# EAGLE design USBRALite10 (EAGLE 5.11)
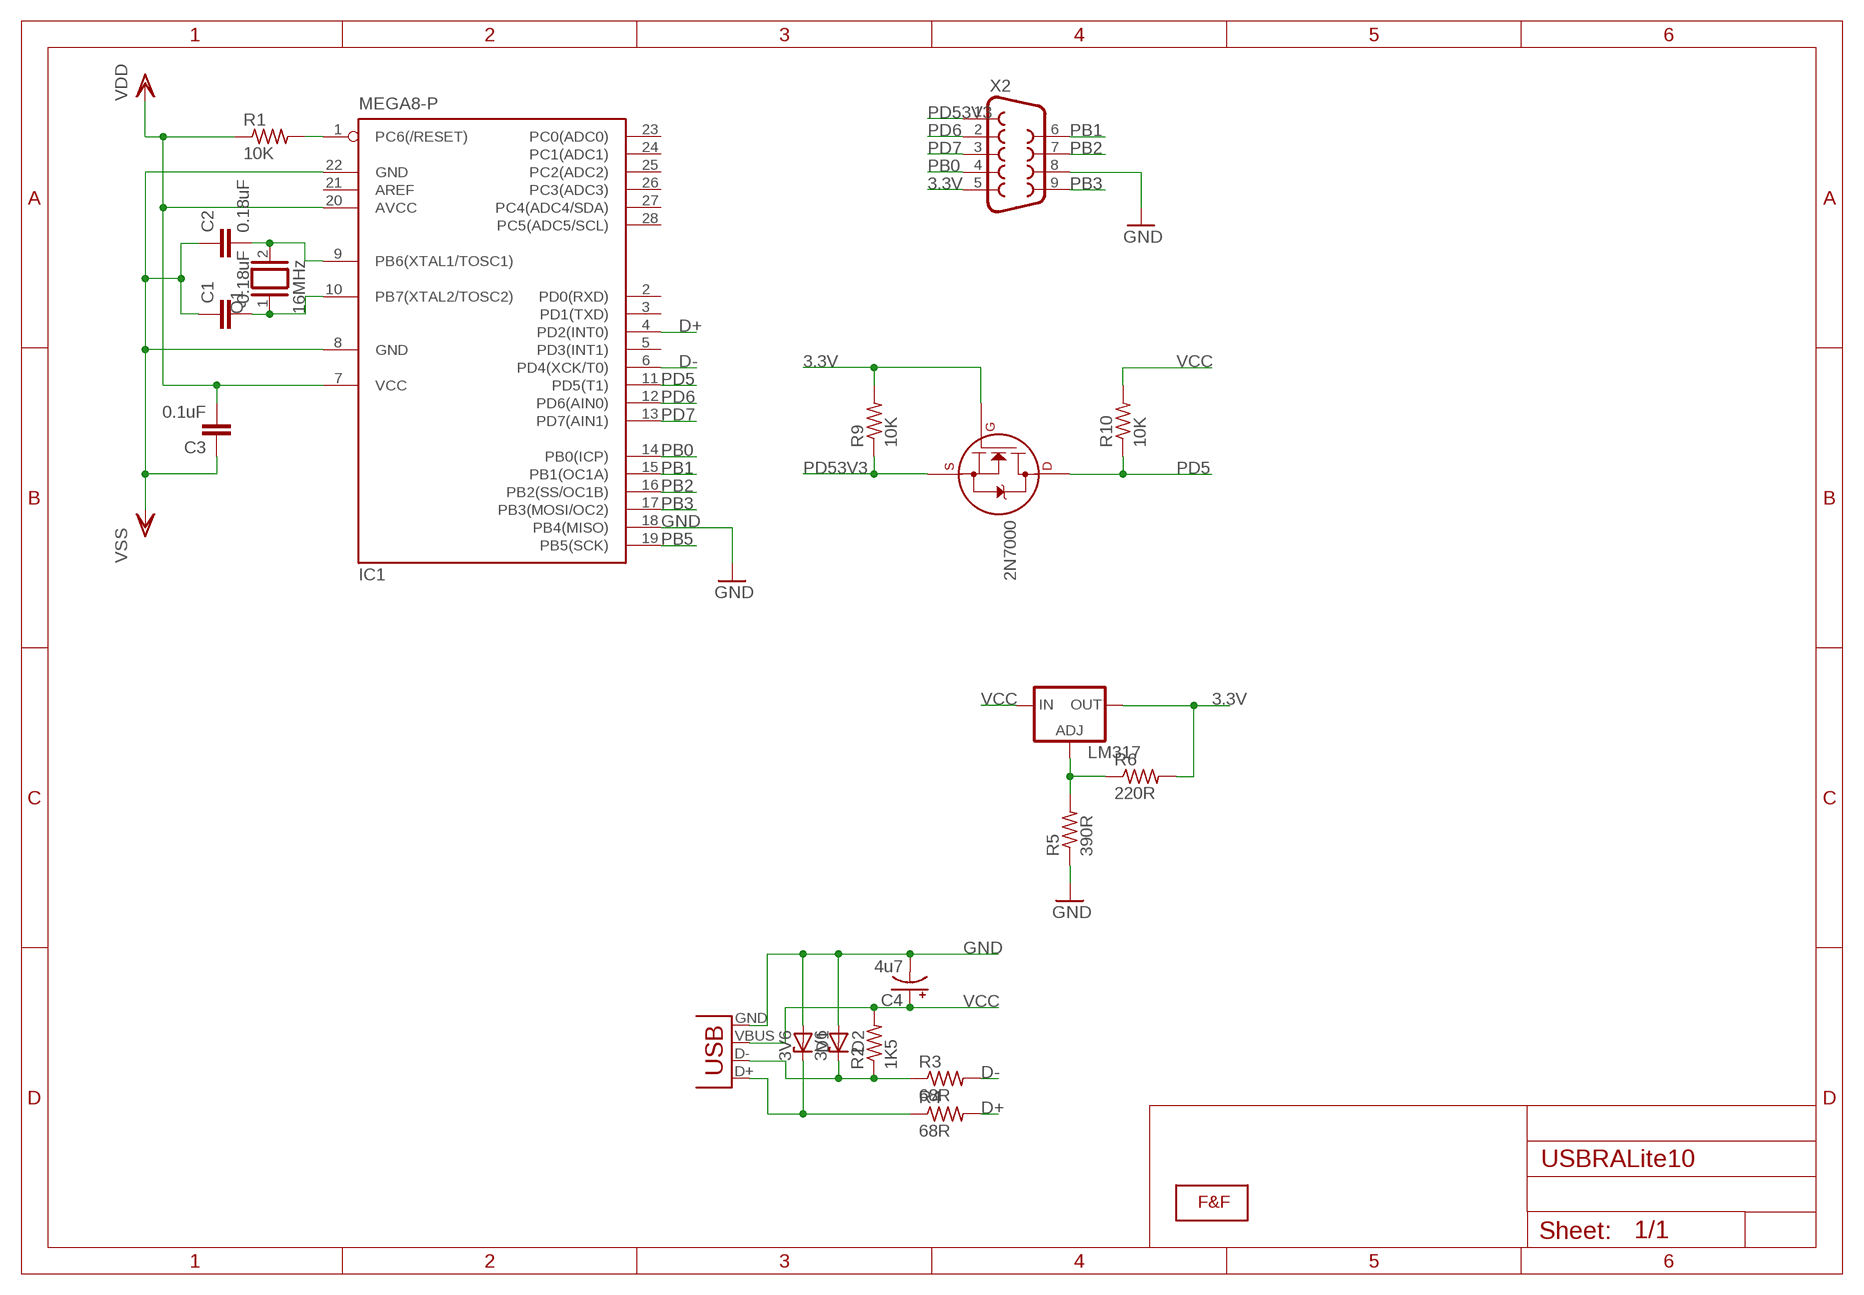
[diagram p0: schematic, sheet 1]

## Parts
2N7000  2N7000_TO92  [TO-92]
C1  0.18uF  CAPPTH  [CAP-PTH-SMALL]
C2  0.18uF  CAPPTH  [CAP-PTH-SMALL]
C3  0.1uF  CAPPTH  [CAP-PTH-SMALL]
C4  4u7  CPOL-USE2.5-6  [E2,5-6]
D1  3V6  ZENER-DIODEZD-5  [ZDIO-5]
D2  3V6  ZENER-DIODEZD-5  [ZDIO-5]
IC1  MEGA8-P  [DIL28-3]
LM317  LM317TS  [317TS]
Q1  16MHz  XTAL/S  [QS]
R1  10K  R-US_0207/10  [0207/10]
R2  1K5  R-US_0207/10  [0207/10]
R3  68R  R-US_0207/10  [0207/10]
R4  68R  R-US_0207/10  [0207/10]
R5  390R  R-US_0207/10  [0207/10]
R6  220R  R-US_0207/10  [0207/10]
R9  10K  R-US_0207/10  [0207/10]
R10  10K  R-US_0207/10  [0207/10]
U$1  LOGOLOGO_WITH_SMOKE_BIG  [LOGO_BIG]
X1  USBPTH  [USB-B-PTH]
X2  DB9MALE  [DB9_MALE]

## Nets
3.3V: 2N7000.2(G) LM317.2(OUT) R6.2 R9.2 X2.5
D+: IC1.4(PD2(INT0)) R4.2
D-: IC1.6(PD4(XCK/T0)) R3.2
GND: C1.1 C2.1 C3.1 C4.- D1.A D2.A IC1.8(GND) IC1.18(PB4(MISO)) IC1.22(GND) R5.1 X1.GND X2.8 ; supply symbol labelled VSS
N$1: IC1.1(PC6(/RESET)) R1.2
N$2: C2.2 IC1.9(PB6(XTAL1/TOSC1)) Q1.2
N$3: C1.2 IC1.10(PB7(XTAL2/TOSC2)) Q1.1
N$5: LM317.1(ADJ) R5.2 R6.1
N$8: D1.C R4.1 X1.D+
N$9: D2.C R2.1 R3.1 X1.D-
PB0: IC1.14(PB0(ICP)) X2.4
PB1: IC1.15(PB1(OC1A)) X2.6
PB2: IC1.16(PB2(SS/OC1B)) X2.7
PB3: IC1.17(PB3(MOSI/OC2)) X2.9
PB5: IC1.19(PB5(SCK))
PD5: 2N7000.3(D) IC1.11(PD5(T1)) R10.1
PD6: IC1.12(PD6(AIN0)) X2.2
PD7: IC1.13(PD7(AIN1)) X2.3
PD53V3: 2N7000.1(S) R9.1 X2.1
VCC: C3.2 C4.+ IC1.7(VCC) IC1.20(AVCC) LM317.3(IN) R1.1 R2.2 R10.2 X1.VBUS ; supply symbol labelled VDD
Unconnected: IC1.2(PD0(RXD)) IC1.3(PD1(TXD)) IC1.5(PD3(INT1)) IC1.21(AREF) IC1.23(PC0(ADC0)) IC1.24(PC1(ADC1)) IC1.25(PC2(ADC2)) IC1.26(PC3(ADC3)) IC1.27(PC4(ADC4/SDA)) IC1.28(PC5(ADC5/SCL))

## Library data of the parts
2N7000 = transistors:2N700*: 2N7000, 2N7002, NDS7002A N-channel enhancement mode MOSFET
C1-C3 = SparkFun:CAP: Capacitor
C4 = adafruit:CPOL-US: POLARIZED CAPACITOR, American symbol
D1 D2 = diode:ZENER-DIODE: Z-Diode
IC1 = atmel:MEGA8-P: MICROCONTROLLER 8 Kbytes FLASH, 1 kbytes SRAM, 512 bytes EEPROM, USART, 4-channel 10 bit ADC, 2-channel 8 bit ADC Pin compatible with Atmega48, ATMega88, ATMega168 Source: avr.lbr; OC_FARNELL: unknown; OC_NEWARK: unknown
LM317 = v-reg:LM317TS: VOLTAGE REGULATOR
Q1 = special:XTAL/S: CRYSTAL
R1-R6 R9 R10 = adafruit:R-US_: RESISTOR, American symbol
U$1 = F&F:LOGO: Faísca e Fumaça Logo
X1 = SparkFun:USB: USB Connectors USB-B-PTH is fully proven SKU : PRT-00139 USB-miniB is fully proven SKU : PRT-00587 USB-A-PCB is untested. USB-A-H is throughly reviewed, but untested. Spark Fun Electronics SKU : PRT-00437 USB-B-SMT is throughly reviewed, but untested. Needs silkscreen touching up. USB-A-S has not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
X2 = SparkFun:DB9: DB9 Connector Standard DB9 (D-Sub 9) serial connector. Can be used for CAN bus as well as RS485 and RS232. Footprint production proven. Spark Fun Electronics SKU : PRT-00429

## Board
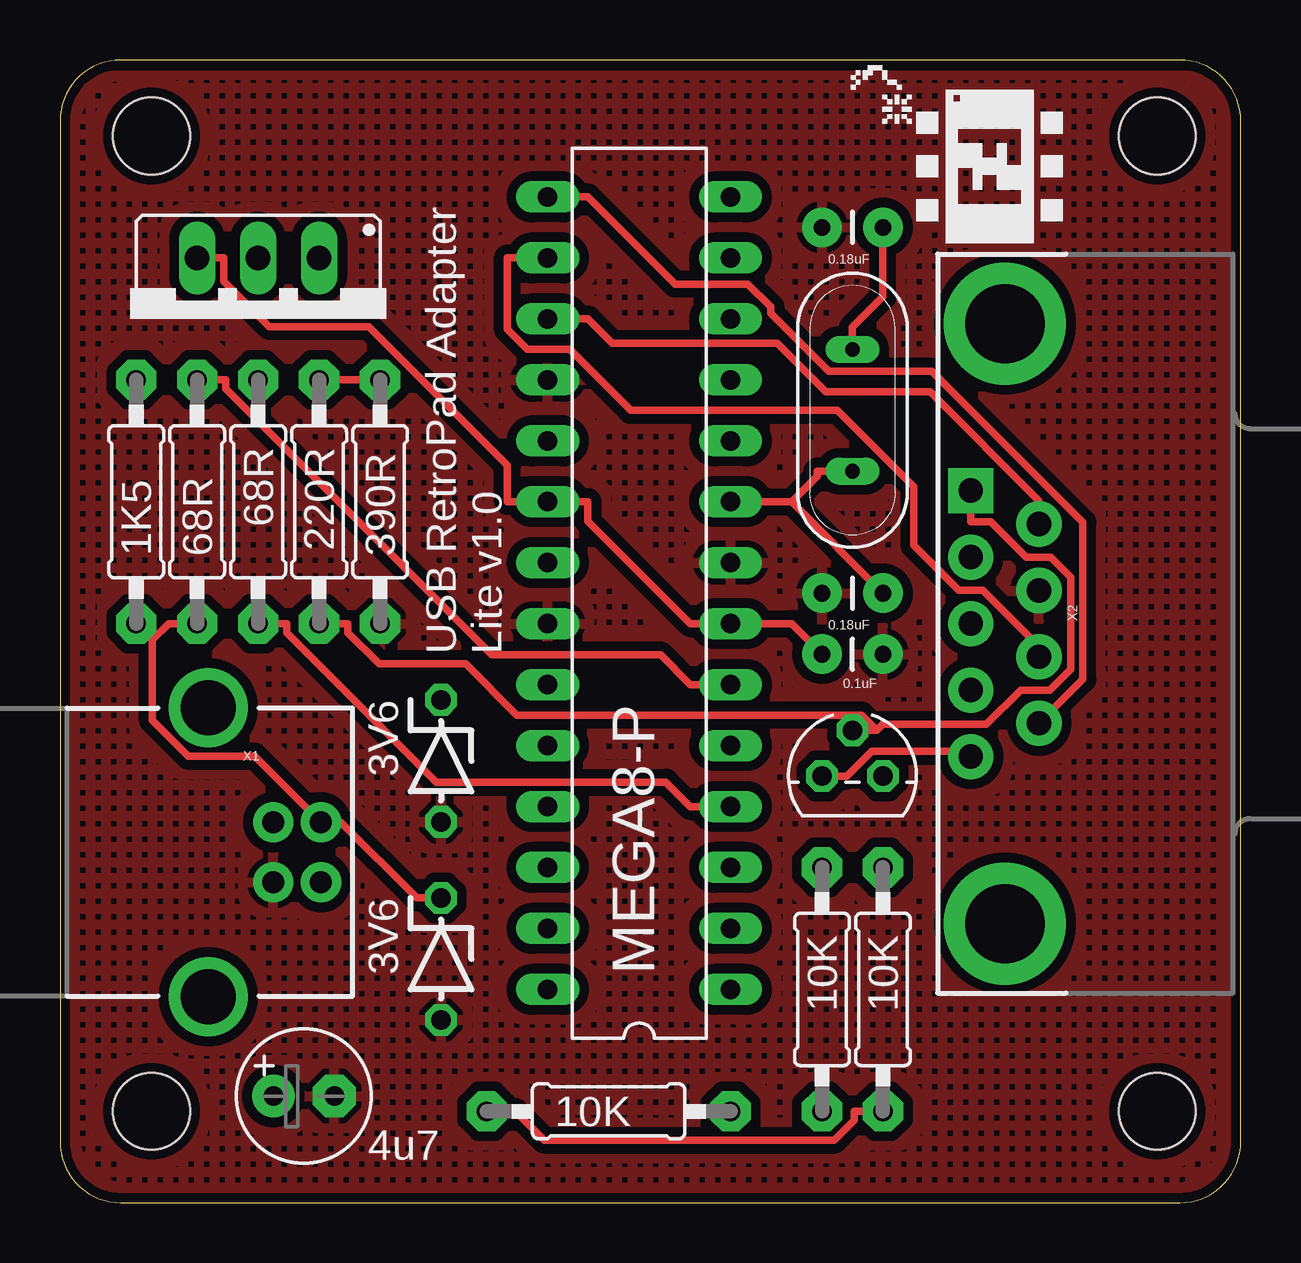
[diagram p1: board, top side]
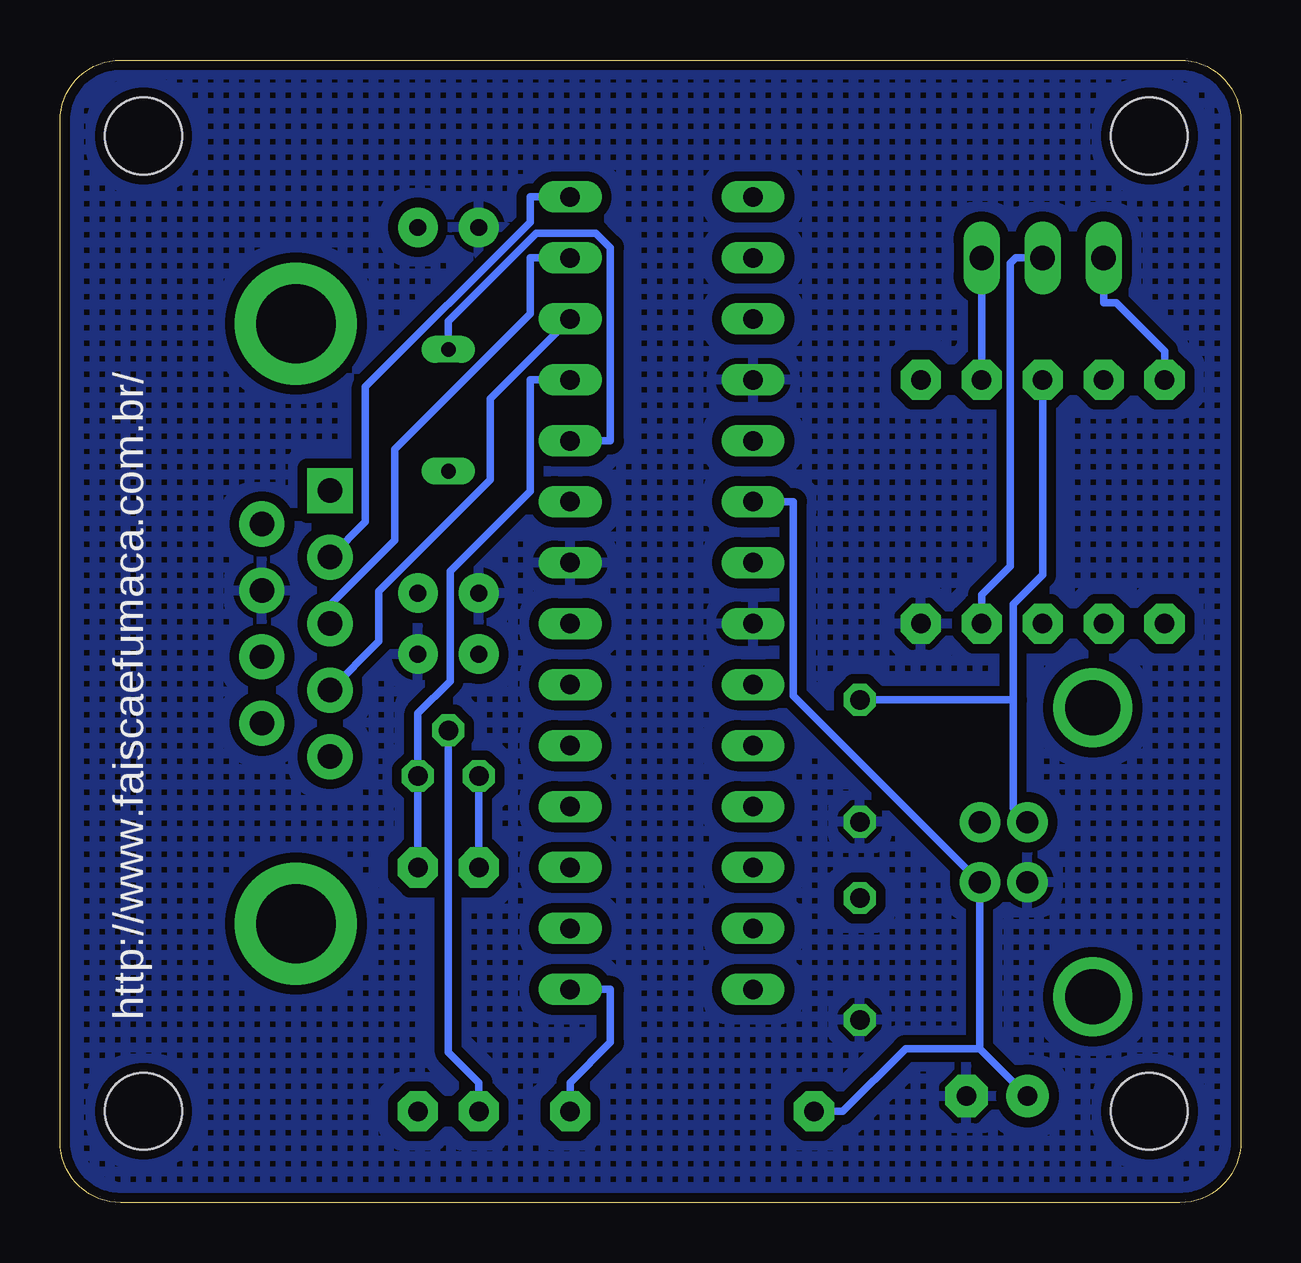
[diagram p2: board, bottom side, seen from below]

Size 49.2 x 47.62 mm. Coordinates in mm from the lower left corner, seen from the top.
Outline: 49.2,45.08 arc90 46.66,47.62 2.54,47.62 arc90 0,45.08 0,2.54 arc90 2.54,0 46.66,0 arc90 49.2,2.54 49.2,45.08
Copper layers (1*16): Top 0.035mm / dielectric 1.5mm / Bottom 0.035mm
Design rules "ITead_rule": minimum track width 6mil, minimum drill 12mil, track to track 6mil, track to pad 6mil, pad to pad 6mil, via to via 6mil, smd to smd 0mil, copper to edge 10mil, drill to drill 10mil, minimum pad ring 10mil, minimum via ring 6mil, stop-mask expansion 2mil, vias tented up to drill 100mil, thermal gap 10mil
Holes 3.2 mm at 3.81,44.45 3.81,3.81 45.72,44.45 45.72,3.81

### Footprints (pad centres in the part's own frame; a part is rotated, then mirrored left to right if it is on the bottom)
TO-92 = drill 0.813 octagon: 1 -1.27,0; 2 0,1.905; 3 1.27,0
CAP-PTH-SMALL = drill 0.7 pad 1.651 round: 1 0,0; 2 2.54,0
E2,5-6 = drill 0.813 pad 1.778 round: + -1.27,0 | drill 0.813 pad 1.778 octagon: - 1.27,0
ZDIO-5 = drill 0.813 octagon: A 2.54,0; C -2.54,0
DIL28-3 = drill 0.813 long: 1 -16.51,-3.81; 2 -13.97,-3.81; 3 -11.43,-3.81; 4 -8.89,-3.81; 5 -6.35,-3.81; 6 -3.81,-3.81; 7 -1.27,-3.81; 8 1.27,-3.81; 9 3.81,-3.81; 10 6.35,-3.81; 11 8.89,-3.81; 12 11.43,-3.81; 13 13.97,-3.81; 14 16.51,-3.81; 15 16.51,3.81; 16 13.97,3.81; 17 11.43,3.81; 18 8.89,3.81; 19 6.35,3.81; 20 3.81,3.81; 21 1.27,3.81; 22 -1.27,3.81; 23 -3.81,3.81; 24 -6.35,3.81; 25 -8.89,3.81; 26 -11.43,3.81; 27 -13.97,3.81; 28 -16.51,3.81
317TS = drill 1.016 long: 1 -2.54,-2.54; 2 0,-2.54; 3 2.54,-2.54
QS = drill 0.61 long: 1 -2.54,0; 2 2.54,0
0207/10 = drill 0.813 pad 1.676 octagon: 1 -5.08,0; 2 5.08,0
USB-B-PTH = drill 0.914 pad 1.676 round: D+ 0,1.25; D- 1.981,1.25; GND 0,-1.25; VBUS 1.981,-1.25 | drill 2.286 round: S1 -2.718,-6.02; S2 -2.718,6.02
DB9_MALE = drill 1.016 pad 1.88 round: 1 5.54,-1.42; 2 2.77,-1.42; 3 0,-1.42; 4 -2.77,-1.42; 6 4.15,1.42; 7 1.38,1.42; 8 -1.38,1.42; 9 -4.15,1.42 | drill 1.016 pad 1.88 square: 5 -5.54,-1.42 | drill 3.302 pad 5.08 round: G1 -12.5,0; G2 12.5,0

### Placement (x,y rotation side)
2N7000  33.02,17.78 0 top
C1  31.75,40.64 0 top
C2  31.75,25.4 0 top
C3  34.29,22.86 180 top
C4  10.16,4.45 0 top
D1  15.88,18.41 270 top
D2  15.88,10.16 270 top
IC1  24.13,25.4 90 top
LM317  8.26,36.83 180 top
Q1  33.02,33.02 270 top
R1  22.86,3.81 0 top
R2  3.17,29.21 90 top
R3  5.71,29.21 90 top
R4  8.26,29.21 270 top
R5  13.34,29.21 90 top
R6  10.79,29.21 270 top
R9  31.75,8.89 270 top
R10  34.29,8.89 270 top
U$1  38.73,43.18 90 top
X1  8.89,14.61 0 top
X2  39.37,24.13 270 top

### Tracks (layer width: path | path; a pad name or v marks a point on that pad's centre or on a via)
3.3V
  Top 0.305: 34.04,19.68 33.4,20.32 19.04,20.32 16.9,22.45 13.29,22.45 11.99,23.76 11.99,24.13 R6.2 | 34.04,19.68 34.28,19.93 38.6,19.93 40.04,21.36 41.25,21.36 42.11,22.23 42.11,26.07 41.29,26.89 40.27,26.89 38.79,28.38 37.95,28.38 X2.5 | 2N7000.2 34.04,19.68
  Bottom 0.305: LM317.2 9.37,39.37 9.6,39.14 9.6,26.52 10.79,25.32 R6.2 | R9.2 31.75,5 33.02,6.27 2N7000.2
D+
  Top 0.305: IC1.4 26.26,16.51 25.25,17.53 15.68,17.53 9.45,23.76 9.45,24.13 R4.2
D-
  Top 0.305: IC1.6 26.26,21.59 25.02,22.83 18,22.83 6.91,33.92 6.91,34.29 R3.2
GND
  pour Bottom (isolate 0.406, hatched): 0,46.99 49.53,46.99 49.53,0 0,0
  pour Top (isolate 0.406, hatched): 0,46.99 49.53,46.99 49.53,0 0,0
N$1
  Bottom 0.305: R1.2 27.94,5 26.26,6.68 26.26,8.89 IC1.1
N$2
  Top 0.305: Q1.2 31.55,30.48 31.55,30.28 30.48,29.21 | 30.48,29.21 C2.2 | 30.48,29.21 29.49,29.21 IC1.9
N$3
  Top 0.305: Q1.1 33.02,36.47 34.29,37.74 C1.2
  Bottom 0.305: IC1.10 26.26,31.75 26.26,39.79 26.87,40.4 29.36,40.4 33.02,36.73 Q1.1
N$5
  Top 0.305: R6.1 R5.2
  Bottom 0.305: R6.1 LM317.1
N$8
  Bottom 0.305: 9.47,20.95 9.47,24.95 8.26,26.16 R4.1 | X1.D+ 9.47,16.44 9.47,20.95 | 9.47,20.95 14.86,20.95 D1.C
N$9
  Top 0.305: 3.85,23.46 4.52,24.13 R3.1 | 3.85,23.46 3.85,20.1 5.34,18.61 8.11,18.61 X1.D- 11.7,15.86 14.86,12.7 D2.C | 3.85,23.46 | 3.85,23.46 R2.1
PB0
  Bottom 0.305: IC1.14 29.62,41.91 29.62,40.86 36.47,34 36.47,28.38 X2.4
PB1
  Top 0.305: IC1.15 22,41.91 25.63,38.28 28.66,38.28 29.62,37.33 29.62,37.06 32.03,34.65 36.33,34.65 42.62,28.35 42.62,21.81 X2.6
PB2
  Top 0.305: IC1.16 18.64,39.37 18.64,36.39 19.47,35.56 21.23,35.56 23.77,33.02 32.38,33.02 35.57,29.82 35.57,27.39 37.45,25.52 38.46,25.52 40.79,23.18 X2.7
PB3
  Top 0.305: IC1.17 22,36.83 23.01,35.81 29.88,35.81 31.91,33.78 36.26,33.78 40.79,29.25 X2.9
PD5
  Bottom 0.305: IC1.11 29.62,34.29 29.62,29.64 32.95,26.31 32.95,21.74 34.29,20.39 2N7000.3 R10.1
PD6
  Bottom 0.305: X2.2 35.91,23.4 35.91,25.48 31.27,30.12 31.27,33.49 IC1.12
PD7
  Bottom 0.305: IC1.13 29.62,39.37 29.62,37.04 35.26,31.39 35.26,27.61 37.95,24.92 X2.3
PD53V3
  Top 0.305: X2.1 37.72,18.82 33.82,18.82 32.78,17.78 2N7000.1
  Bottom 0.305: R9.1 2N7000.1
VCC
  Top 0.305: LM317.3 6.83,39.37 6.83,38.39 8.72,36.5 12.86,36.5 18.64,30.72 18.64,29.21 20.28,29.21 IC1.20 22,29.21 22,28.4 26.26,24.13 IC1.7 30.48,24.13 C3.2 | R10.2 33.1,3.81 33.1,3.44 32.27,2.61 20.18,2.61 18.97,3.81 R1.1
  Bottom 0.305: R1.1 16.59,3.81 13.97,6.43 10.87,6.43 | 10.87,6.43 X1.VBUS 18.64,21.13 18.64,29.21 IC1.20 | C4.+ 10.87,6.43 | LM317.3 5.71,37.49 5.18,37.49 3.17,35.48 R2.2

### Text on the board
tPlace: USB RetroPad Adapter | Lite v1.0
bPlace: http://www.faiscaefumaca.com.br/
